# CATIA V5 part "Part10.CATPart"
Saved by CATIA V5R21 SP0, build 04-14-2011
Part number: Part1
Material "DS Light Blue": density 7860 kg/m3, Young's modulus 2e+11 Pa, Poisson ratio 0.266
Bounding box of the stored display mesh (mm): x 0 to 5, y -75.588 to 55, z -18.997 to 81.997
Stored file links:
  C:\Users\RIAD MAHAMUD PIASH\Desktop\Part10.CATPart
  C:\Program Files (x86)\Dassault Systemes\B21\intel_a\startup\materials\Catalog.CATMaterial
  C:\Program Files (x86)\Dassault Systemes\B21\intel_a\startup\materials\blue_env_512x512.jpg
  C:\Program Files (x86)\Dassault Systemes\B21\intel_a\startup\materials\red_env_512x512.jpg
  C:\Program Files (x86)\Dassault Systemes\B21\intel_a\startup\materials\yellow_env_512x512.jpg
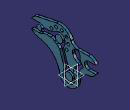
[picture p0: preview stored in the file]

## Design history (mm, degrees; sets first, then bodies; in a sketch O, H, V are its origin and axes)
Body1 (main body), material "DS Light Blue"
  Sketch1 on yz-plane, origin (0, 0, 0), H (0, 1, 0), V (0, 0, 1)
    circle A1 centre (0, 0) radius 7.5
    arc A2 centre (0, 0) radius 12.5 from (12.5, 0) to (4.7142, 11.577) ccw
    arc A3 centre (0, 0) radius 19 from (-18.767, -2.9661) to (18.961, -1.2167) ccw
    circle A4 centre (-20, 56) radius 7.5
    point P1 (-20, 56)
    arc A5 centre (-20, 56) radius 12.5 from (-9.0185, 50.0286) to (-7.5, 56) ccw
    construction line L1 (0, 0) -> (-20, 56)
    line L2 (-9.6508, 41.8882) -> (-0.9318, 17.4752)
    arc A6 centre (-0.2333, 45.2516) radius 10 from (-9.0185, 50.0286) to (-9.6508, 41.8882) ccw
    point P2 (-9.0185, 50.0286)
    point P3 (-9.6508, 41.8882)
    arc A7 centre (8.4856, 20.8385) radius 10 from (4.7142, 11.577) to (-0.9318, 17.4752) cw
    point P6 (4.7142, 11.577)
    point P7 (-0.9318, 17.4752)
    point P8 (12.5, 0)
    point P10 (-10.9815, 5.9714)
    point P11 (-9.6719, -7.9186)
    arc A8 centre (0, 0) radius 12.5 from (-9.6719, -7.9186) to (-10.9815, 5.9714) cw
    point P13 (-10.3492, 14.1118)
    arc A9 centre (-19.7667, 10.7484) radius 10 from (-10.9815, 5.9714) to (-10.3492, 14.1118) ccw
    point P15 (-19.0682, 38.5248)
    line L3 (-19.0682, 38.5248) -> (-10.3492, 14.1118)
    point P16 (-24.7142, 44.423)
    arc A10 centre (-28.4856, 35.1615) radius 10 from (-24.7142, 44.423) to (-19.0682, 38.5248) cw
    arc A11 centre (-20, 56) radius 12.5 from (-24.7142, 44.423) to (-29.3169, 47.6667) cw
    arc A12 centre (-20, 56) radius 12.5 from (-7.5, 56) to (-27.9871, 65.6154) ccw
    arc A13 centre (0, 0) radius 12.5 from (-9.6719, -7.9186) to (12.5, 0) ccw
    circle A14 centre (-60, 56) radius 5
    point P19 (-60, 56)
    arc A15 centre (-60, 56) radius 9 from (-55.4389, 63.7586) to (-60, 65) ccw
    construction line L4 (-60, 56) -> (-20, 56)
    point P20 (-20, 56)
    line L5 (-45.3031, 61) -> (-40.7666, 61)
    arc A16 centre (-45.3031, 81) radius 20 from (-55.4389, 63.7586) to (-45.3031, 61) ccw
    arc A17 centre (-40.7666, 81) radius 20 from (-27.9871, 65.6154) to (-40.7666, 61) cw
    line L6 (-45.3031, 51) -> (-36.7705, 51)
    arc A18 centre (-45.3031, 31) radius 20 from (-55.4389, 48.2414) to (-45.3031, 51) cw
    point P30 (-31.4564, 51)
    arc A19 centre (-36.7705, 41) radius 10 from (-29.3169, 47.6667) to (-36.7705, 51) ccw
    point P34 (-1.4564, 18.9441)
    point P35 (-10.8739, 15.5807)
    arc A20 centre (-20, 56) radius 26 from (4.3555, 65.1) to (-25.2, 81.4747) ccw
    point P36 (-20, 56)
    arc A21 centre (-60, 56) radius 18 from (-75.5885, 47) to (-61.9253, 38.1033) ccw
    line L7 (-63.6, 73.6363) -> (-25.2, 81.4747)
    point P38 (-63.6, 73.6363)
    line L8 (-75.5885, 65) -> (-60, 65)
    point P39 (-60, 65)
    point P40 (-75.5885, 65)
    point P41 (-60, 47)
    point P42 (-75.5885, 47)
    line L9 (-75.5885, 47) -> (-60, 47)
    arc A22 centre (-60, 56) radius 9 from (-60, 47) to (-55.4389, 48.2414) ccw
    arc A23 centre (-67.1663, -10.6156) radius 49 from (-61.9253, 38.1033) to (-18.767, -2.9661) cw
    arc A24 centre (-60, 56) radius 18 from (-63.6, 73.6363) to (-75.5885, 65) ccw
    arc A25 centre (40, 39) radius 17 from (41.5825, 22.0738) to (55, 31) ccw
    point P46 (40, 39)
    arc A26 centre (40, 39) radius 8 from (40, 47) to (40, 31) ccw
    line L10 (55, 47) -> (40, 47)
    axis line L11 (40, 39) -> (158.9192, 39)
    point P48 (55, 47)
    point P49 (40, 47)
    point P50 (40, 31)
    point P51 (55, 31)
    line L12 (55, 31) -> (40, 31)
    point P52 (55, 47)
    line L13 (17.47, 56) -> (40, 56)
    point P53 (40, 56)
    arc A27 centre (17.47, 70) radius 14 from (4.3555, 65.1) to (17.47, 56) ccw
    arc A28 centre (43.9097, -2.8176) radius 25 from (18.961, -1.2167) to (41.5825, 22.0738) cw
    arc A29 centre (40, 39) radius 17 from (55, 47) to (40, 56) ccw
    point P60 (40, 56)
    radius A3 = 19
    radius A1 = 7.5
    radius A2 = 12.5
    radius A4 = 7.5
    radius A5 = 12.5
    distance P1 V = 20
    distance P1 H = 56
    distance L2 L1 = 5
    radius A6 = 10
    radius A7 = 10
    radius A14 = 5
    radius A15 = 9
    distance L5 L4 = 5
    distance P20 P19 = 40
    radius A16 = 20
    radius A17 = 20
    distance P19 H = 56
    distance L4 L6 = 5
    radius A18 = 20
    radius A19 = 10
    radius A20 = 26
    radius A21 = 18
    distance L8 L4 = 9
    radius A23 = 49
    radius A26 = 8
    distance P46 H = 39
    distance P46 V = 40
    distance P46 L10 = 8
    distance L13 L11 = 17
    radius A27 = 14
    radius A28 = 25
    tangency: A6 A5, A6 L2, A7 L2, A7 A2, A12 A6, A13 A7, A16 A15, A16 L5, A17 A12, A17 L5, A18 A15, A18 L6, A19 L6, L7 A20, L7 A21, A23 A21, A23 A3, A24 L7, A27 A20, A27 L13, A28 A3, A28 A25, A29 L4
    symmetry: P6 P10 L1, P8 P11 L1, A2 A8 L1, P7 P13 L1, A7 A9 L1, P3 P15 L1, L2 L3 L1, P2 P16 L1, A6 A10 L1, A5 A11 L1, P39 P41 L4, P40 P42 L4, L8 L9 L4, P49 P50 L11, P48 P51 L11, L10 L12 L11
    coincidence: P20 L1, P30 L6, L2 P34, L3 P35, P36 L4, P36 P20, A21 P38, A15 A22, A21 P40, A3 P35, A25 P48, L10 P52, A25 P53, A3 P34, A25 P52, P53 P60
    horizontal: L4 H, L5 H, L6 H, L8 H, L10 H, L11 H, L13 H
  Pad1: profile Sketch1, direction (1, 0, 0), length 5
  Sketch2 on end face of Pad1, origin (5, 0, 0), H (0, 1, 0), V (0, 0, 1)
    construction circle A1 centre (-20, 56) radius 19
    point P1 (-20, 56)
    circle A2 centre (-1, 56) radius 3
    point P2 (-1, 56)
    circle A3 centre (-4.6287, 67.1679) radius 3
    circle A4 centre (-14.1287, 74.0701) radius 3
    circle A5 centre (-25.8713, 74.0701) radius 3
    circle A6 centre (-35.3713, 67.1679) radius 3
    circle A7 centre (-4.6287, 44.8321) radius 3
    radius A1 = 19
    distance P1 V = 20
    distance P1 H = 56
    radius A2 = 3
    distance P2 P1 = 19
    distance P2 H = 56
  Pocket1: profile Sketch2, direction (-1, 0, 0), length 5
  Sketch3 on end face of Pad1, origin (5, 0, 0), H (0, 1, 0), V (0, 0, 1)
    point P1 (15, 15)
    arc A1 centre (25, 31) radius 4.07 from (29.07, 31) to (27.5783, 34.1492) ccw
    point P2 (25, 31)
    arc A2 centre (15, 47) radius 8 from (22.929, 45.9364) to (23, 47) ccw
    point P3 (15, 47)
    arc A3 centre (35.8136, 44.208) radius 13 from (27.5783, 34.1492) to (22.929, 45.9364) cw
    arc A4 centre (25, 31) radius 4.07 from (27.3468, 27.6747) to (29.07, 31) ccw
    arc A5 centre (35.9958, 15.4193) radius 15 from (27.3468, 27.6747) to (20.9958, 15.4433) ccw
    arc A6 centre (15, 47) radius 8 from (23, 47) to (7.4472, 44.3628) ccw
    arc A7 centre (26.3292, 50.9558) radius 20 from (7.4472, 44.3628) to (18.4659, 32.5664) ccw
    arc A8 centre (16.9734, 29.9641) radius 3 from (18.4659, 32.5664) to (18.5316, 27.4005) cw
    arc A9 centre (23.8522, 13.3758) radius 15 from (18.5316, 27.4005) to (9.1957, 16.5673) ccw
    arc A10 centre (15, 15) radius 6.0122 from (9.1957, 16.5673) to (20.9958, 15.4433) ccw
    distance P1 H = 15
    distance P1 V = 15
    radius A1 = 4.07
    distance P2 V = 25
    distance P2 H = 31
    radius A2 = 8
    distance P3 V = 15
    distance P3 H = 47
    radius A3 = 13
    radius A5 = 15
    radius A7 = 20
    radius A8 = 3
    radius A9 = 15
    tangency: A3 A1, A3 A2, A4 A3, A5 A4, A6 A3, A6 A7
    coincidence: A7 P2
  Pocket2: profile Sketch3, direction (-1, 0, 0), length 5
